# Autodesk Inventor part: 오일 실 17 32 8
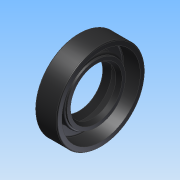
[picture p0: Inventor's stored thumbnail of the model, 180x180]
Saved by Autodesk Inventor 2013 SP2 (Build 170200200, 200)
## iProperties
Created: 2026-07
Part Number: 오일 실 17 32 8
Material: Generic
Document SubType Name: Modeling
Designer: a
Density: 1 g/cm^3
Author: a
변환 표준: STEP AP214IS
전처리기: Build: 200, Release: 2013 SP2 Update 6 - Date: Thu 07/17/2014
전송 단위: 밀리미터
불확실성: 0.01
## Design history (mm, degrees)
node "오일 실 17 32 81"
body "Solid1"
node "기준1"
